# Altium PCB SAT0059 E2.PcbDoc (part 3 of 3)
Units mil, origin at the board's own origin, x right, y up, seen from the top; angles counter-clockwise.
Board outline 3960.27 x 3100.03 mil, 6 copper layers (Top Layer, GND, Power, Inner Routing, GND 2, Bottom Layer), stack 59.2 mil thick; 276 components, 209 nets, 812 pads, 621 vias.
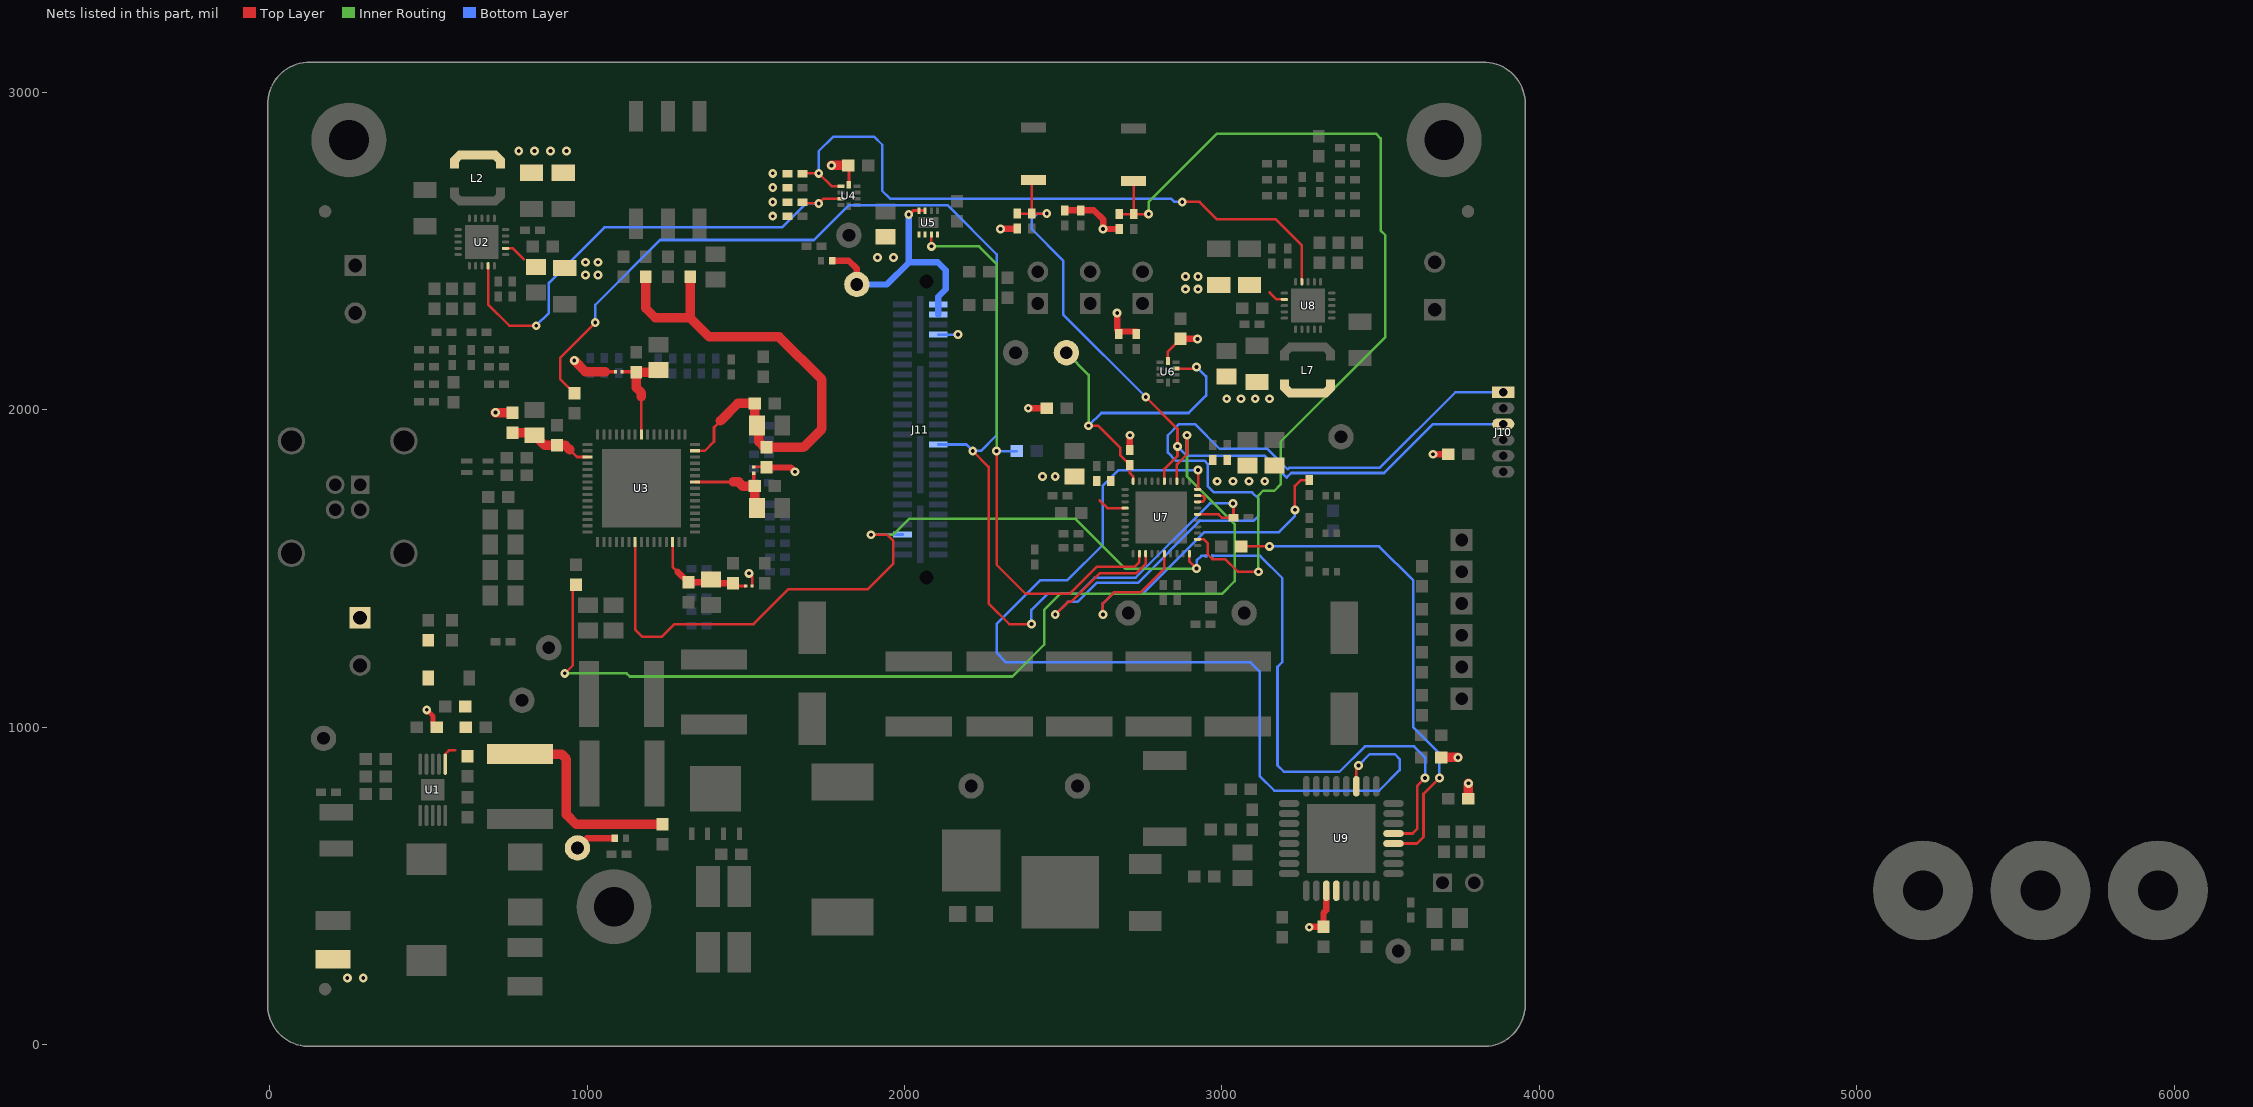
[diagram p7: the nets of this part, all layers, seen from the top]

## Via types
v1: diameter 28, hole 12, Top Layer to Bottom Layer, 528 vias
v2: diameter 19.68, hole 7.87, Top Layer to Bottom Layer, 44 vias
v3: diameter 23.62, hole 11.81, Top Layer to Bottom Layer, 25 vias
v4: diameter 19.68, hole 7.87, Top Layer to Bottom Layer, tented both sides, 20 vias
v5: diameter 18.75, hole 7.87, Top Layer to Bottom Layer, 4 vias

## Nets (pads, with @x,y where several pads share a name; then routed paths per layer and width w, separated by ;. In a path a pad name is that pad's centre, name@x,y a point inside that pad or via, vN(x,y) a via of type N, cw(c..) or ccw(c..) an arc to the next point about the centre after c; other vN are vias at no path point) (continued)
SDA_DRV2667_1: R36.1 U4.1 U8.19 | length 2093.6
  Top Layer w8: R36.1@1676.37,2745 R36.1@1679.35,2745 ; R36.1@1678.34,2743.99 R36.1@1679.35,2745 ; U4.1@1799.8,2704.53 1770.47,2704.53 v1(1730,2745) R36.1@1679.35,2745 ; v1(2875,2655) 2930,2655 2985,2600 3170,2600 3251.68,2518.32 U8.19@3251.68,2403.08
  Bottom Layer w8: v1(1730,2745) 1730,2815 1775,2860 1905,2860 1930,2835 1930,2690 1955,2665 2840,2665 2850,2655 v1(2875,2655)
SDA_DRV2667_2: R38.1 U2.19 U4.3 | length 1535.6
  Top Layer w8: U2.19@688.18,2453.55 688.18,2331.82 755,2265 v1(840,2265) ; R38.1@1676.37,2651.01 1731.01,2651.01 1745.16,2665.16 U4.3@1799.8,2665.16
  Bottom Layer w8: v1(840,2265) 880,2305 880,2400 1055,2575 1614.8,2575 1689.8,2650 v1(1730,2650)
SDA_UC: R50.1 SDA.1 U6.8 U7.10 | length 1088.3
  Top Layer w8: v1(2580,1950) 2610,1950 2680,1880 2680,1856.38 R50.1@2710,1826.38 2710,1800.79 2720.42,1790.37 U7.10@2720.42,1775.17 ; U6.8@2855.2,2129.84 2914.84,2129.84 v1(2920,2135)
  Inner Routing w8: SDA.1@2510,2180 2580,2110 v1(2580,1950)
  Bottom Layer w8: v1(2580,1950) 2620,1990 2895,1990 2950,2045 2950,2105 v1(2920,2135)
SQW: U9.4
SYNC: R59.2 U9.12 | length 1551.3
  Top Layer w8: R59.2@3061.5,1570 v1(3150,1570) ; U9.12@3540.31,633.94 3613.94,633.94 3635,655 3635,790 v1(3685,840)
  Bottom Layer w8: v1(3150,1570) 3495,1570 3602.8,1462.2 3602.8,999.48 3685,917.28 v1(3685,840)
TDIO: C50.1 J10.3 R41.1 RESET.1 U7.5 | length 2423.3
  Top Layer w8: R41.1@2356,2618.26 C50.1@2401,2618.26 ; RESET.1@2406,2723.34 2401,2718.34 C50.1@2401,2618.26 ; v1(2448.26,2618.26) C50.1@2401,2618.26 ; v1(2760,2040) 2860,1940 v1(2860,1885) 2860,1855 2818.84,1813.84 U7.5@2818.84,1775.17
  Bottom Layer w8: v1(2448.26,2618.26) 2418.7,2618.26 2401,2600.56 2401,2569 2500,2470 2500,2300 v1(2760,2040) ; v1(2860,1885) 2890,1855 3135,1855 3203.69,1786.31 3218.37,1801 3511,1801 3665,1955 J10.3@3886,1955
TSC_INT: J11.30 R23.1 R60.2 U7.36 | length 4230.3
  Top Layer w8: R23.1@960,2051.5 915,2096.5 915,2163.94 v1(1026.06,2275) ; v1(2215,1870.52) 2265,1820.52 2265,1390 2330,1325 v1(2400,1325) ; U7.36@2923.17,1670.84 2989.16,1670.84 3000,1660 R60.2@3036.38,1660 3036.38,1703.62 v1(3035,1705)
  Bottom Layer w8: v1(1026.06,2275) 1026.06,2331.06 1230,2535 1715,2535 1825,2645 2135,2645 2290,2490 2290,1920 2240.52,1870.52 v1(2215,1870.52) 2194.76,1890.76 J11.30@2106.1,1890.76 ; v1(2400,1325) 2400,1370 2450,1420 2547.37,1420 2598.37,1471 2728.37,1471 2962.37,1705 v1(3035,1705)
"TX (RX)": J10.1 U7.23 | length 2877.3
  Top Layer w8: v1@2472.5,1357.5 v1(2475,1355) ; v1@2477.5,1357.5 2515,1395 2525,1395 2615,1485 2730,1485 2759.79,1514.79 U7.23@2759.79,1546.83
  Bottom Layer w8: v1(2475,1355) 2515,1395 2545,1395 2605,1455 2735,1455 2930,1650 3100,1650 3115,1665 3115,1720 3095,1740 2975,1740 2955,1760 2955,1830 2946,1839 2856,1839 2830,1865 2830,1920 2865,1955 2915,1955 2993.19,1876.81 3143.19,1876.81 3207.37,1812.63 3211.75,1817 3497,1817 3735,2055 J10.1@3886,2055
UC_INT: R24.1 U7.3 | length 3271.8
  Top Layer w8: v1(930,1170) 955,1195 R24.1@955,1448.5 ; U7.3@2858.21,1775.17 2858.21,1828.21 2890,1860 v1(2890,1920)
  Inner Routing w8: v1(930,1170) 1125,1170 1135,1160 2340,1160 2440,1260 2440,1370 2490,1420 3000,1420 3040,1460 3040,1640 3033.46,1646.54 2890,1790 v1(2890,1920)
USER_BUTTON: C55.1 R49.1 U7.32 USER.1 | length 2871.9
  Top Layer w8: R49.1@2677,2616.62 C55.1@2722,2616.62 ; USER.1@2722,2720.32 C55.1@2722,2616.62 ; v1(2769.26,2616.62) C55.1@2722,2616.62 ; U7.32@2923.17,1592.1 2942.9,1592.1 2955,1580 2955,1545 2970,1530 3010,1530 3050,1490 v1(3115,1490)
  Inner Routing w8: v1(2769.26,2616.62) 2769.26,2654.26 2985,2870 3485,2870 3500,2855 3500,2565 3515,2550 3515,2229.5 3185,1899.5 3185,1765 3165,1745 3130,1745 3115,1730 v1(3115,1490)
USER_LED: R66.2 U7.26 | length 1223
  Top Layer w8: v1(2625,1355) 2625,1390 2660,1425 2744.13,1425 2818.84,1499.71 U7.26@2818.84,1546.83 ; v1(3230,1685) 3230,1760 3248.62,1778.62 R66.2@3275,1778.62
  Bottom Layer w8: v1(2625,1355) 2625,1390 2655,1420 2750,1420 2945,1615 3180,1615 3230,1665 v1(3230,1685)
V_BATTERY: D1.2 J3.1 R8.2
VCC_LCD: D8.2 J11.2 J11.4 TP3.1 U5.7 U5.8 | length 812.6
  Top Layer w10: v1@2015,2615 2027.4,2627.4 U5.8@2045.47,2627.4 U5.7@2065.16,2627.4
  Top Layer w20: D8.2@1772.72,2470 1825,2470 1850,2445 TP3.1@1850,2395
  Bottom Layer w20: TP3.1@1850,2395 1945,2395 2015,2465 ; v1(2013.43,2615) 2013.43,2466.57 2015,2465 ; J11.4@2106.1,2300.2 J11.2@2106.1,2331.7 2106.1,2356.1 2130,2380 2130,2440 2105,2465 2015,2465
VD: J11.47 NT4.2 U3.7 U7.30 | length 2670
  Top Layer w8: U3.7@1151.67,1583.72 1151.67,1308.33 1175,1285 1235,1285 1275,1325 1525,1325 1635,1435 1884.76,1435 1965,1515.24 1965,1586.74 1945.16,1606.58 v1(1895,1606.58) ; U7.30@2897.58,1546.83 2897.58,1522.42 v1(2920,1500)
  Inner Routing w8: v1(1895,1606.58) 1965,1606.58 2014.72,1656.3 2538.7,1656.3 2695,1500 v1(2920,1500)
  Bottom Layer w8: v1@1895,1607.29 J11.47@1993.9,1607.29 ; v1(2920,1500) 2920,1525 2935,1540 NT4.2@2950,1540
VDC_LCD_EN: R111.1 U5.3 U7.22 | length 1833.3
  Top Layer w8: v1@2084.84,2515 U5.3@2084.84,2552.6 ; v1(2290,1870) 2290,1512 2382,1420 2520,1420 2605,1505 2725,1505 2740.1,1520.1 U7.22@2740.1,1546.83
  Inner Routing w8: v1(2085,2515) 2235,2515 2290,2460 v1(2290,1870)
  Bottom Layer w8: v1(2290,1870) R111.1@2353.5,1870
VDD: C23.1 C25.1 C26.1 C28.1 C43.1 C44.1 C52.1 C53.1 C56.1 C58.1 C59.1 C60.1 C61.1 C64.1 C65.1 C66.1 C70.1 C76.2 J11.8 L2.2 L4.2 L5.2 L7.2 NT1.1 NT2.1 NT3.1 R1.2 R5.1 R36.2 R37.2 R38.2 R39.2 R41.2 R47.2 R48.2 R49.2 R50.2 R51.2 R78.1 R80.2 R81.1 R109.2 R110.2 R114.1 TP1.1 U2.2 U4.10 U5.1 U5.2 U5.4 U6.10 U7.14 U7.38 U7.39 U8.2 U9.3 VDD.2 | length 1967.3
  Top Layer w8: U2.2@743.3,2508.67 766.33,2508.67 800,2475 ; v1(1510,1485) 1520,1475 NT2.1@1520,1445 ; NT3.1@1525,1820 1563.5,1820 L5.2@1565,1818.5 ; 2615,1715 2639.47,1690.53 U7.14@2694.83,1690.53 ; U6.10@2830,2153.86 2830,2183.5 C56.1@2870,2223.5 ; U7.38@2921.7,1710.21 2936.85,1710.21 ccw(c2935.33,1720.06) 2936.85,1729.9 U7.39@2921.7,1729.9 ; 3150,2370 3172.04,2347.96 U8.2@3196.56,2347.96
  Top Layer w10: 1056.63,2120 NT1.1@1090,2120 ; C43.1@1823.5,2770 1825,2768.5 1825,2735 U4.10@1825,2708.86
  Top Layer w15: v1(495,1055) 515,1035 515,1011.5 R5.1@526.5,1000
  Top Layer w20: TP1.1@970,620 1000,650 VDD.2@1087.28,650 ; L5.2@1565,1818.5 1641.5,1818.5 v1(1655,1805) ; v1(2302.65,2570.02) R41.2@2354.03,2570.02 ; v1(2390,2005) R114.1@2448.5,2005 ; R109.2@2505,2628.62 R110.2@2555,2628.62 2596.38,2628.62 2625.62,2599.38 v1(2625.62,2569.38) R49.2@2677,2569.38 ; v1(2670,2305) 2670,2251.5 2675,2246.5 R51.2@2730,2246.5 ; R50.2@2710,1873.62 v1(2710,1920) ; C56.1@2870,2223.5 v1(2923.5,2223.5) ; v1(3275,370) 3276.5,371.5 C76.2@3320,371.5 3320,415 3328.7,423.7 U9.3@3328.7,485.31 ; v1(3665,1860) R80.2@3713.5,1860
  Top Layer w30: v1(711.5,1991.5) L4.2@765,1991.5 ; v1(960,2155) 995,2120 1056.63,2120 ; v1(1770,2770) C43.1@1823.5,2770 ; R78.1@3693.5,906.5 3695,905 v1(3743.5,905) ; R81.1@3775,773.5 R81.1@3776.5,775 v1(3776.5,823.5)
  Bottom Layer w8: J11.8@2106.1,2237.21 v1(2168.78,2237.21)
  other v1: 245,210 295,210 2985,1775 3035,1775 3085,1775 3135,1775 2435,1790 2475,1790 3015,2035 3060,2035 3105,2035 3150,2035 2885,2380 2925,2380 2885,2420 2925,2420 995,2425 1035,2425 995,2465 1035,2465 1915,2480 1965,2480 1585,2610 1585,2655 1585,2700 1585,2745 785,2815 835,2815 885,2815 935,2815
VDD33_A: C24.1 C27.1 L4.1 U3.48 | length 269
  Top Layer w8: 945,1875 968.56,1851.44 U3.48@1002.06,1851.44
  Top Layer w30: L4.1@765,1928.5 826.5,1928.5 C24.1@835,1920 866.5,1888.5 C27.1@905,1888.5 931.5,1888.5 945,1875
VDD33_B: C38.1 C40.1 L5.1 R26.2 R28.2 U3.29 | length 1662.2
  Top Layer w8: U3.29@1340.65,1871.12 1371.12,1871.12 1400,1900 1400,1945 1420,1965
  Top Layer w30: R26.2@1185,2418.5 1185,2370 1185,2320 1215,2290 1325,2290 ; R28.2@1325,2418.5 1325,2290 ; 1420,1965 1475,2020 C38.1@1528.5,2020 1528.5,1956.5 C40.1@1535,1950 1541,1944 1541,1900 1559.5,1881.5 L5.1@1565,1881.5 1681.5,1881.5 1740,1940 1740,2095 1605,2230 1385,2230 1325,2290
VDDIO1: C36.1 C37.1 NT2.2 R32.2 U3.13 | length 340.7
  Top Layer w8: U3.13@1269.78,1583.72 1269.78,1505.22 1285,1490
  Top Layer w10: R32.2@1460,1453.5 1468.5,1445 NT2.2@1500,1445
  Top Layer w20: 1285,1490 1318.5,1456.5 C36.1@1320,1456.5 1381.5,1456.5 C37.1@1390,1465 1401.5,1453.5 R32.2@1460,1453.5
VDDIO2: C39.1 C41.1 NT3.2 U3.24 | length 298.1
  Top Layer w8: U3.24@1340.65,1772.7 1460,1772.7
  Top Layer w10: NT3.2@1525,1800 1525,1763.5 C39.1@1528.5,1760
  Top Layer w30: 1460,1772.7 1477.3,1772.7 1490,1760 C39.1@1528.5,1760 C41.1@1528.5,1696.5
VDDIO3: C33.1 C34.1 NT1.2 U3.38 | length 321.3
  Top Layer w8: U3.38@1171.35,1922.3 1171.35,2041.35
  Top Layer w10: NT1.2@1110,2120 1153.5,2120 C33.1@1155,2118.5
  Top Layer w30: 1171.35,2041.35 1171.35,2053.65 1155,2070 C33.1@1155,2118.5 1218.5,2118.5 C34.1@1225,2125
VDDIO/EN: U7.40 U9.19 | length 3018.5
  Top Layer w8: U7.40@2925,1751.41 v1(2925,1810) ; U9.19@3423.19,814.06 3423.19,873.19 v1(3430,880)
  Bottom Layer w8: v1(2925,1810) 2673.8,1810 2625,1761.2 2625,1575 2512.5,1462.5 2427.5,1462.5 2290,1325 2290,1235 2320.39,1204.61 3090.39,1204.61 3119,1176 3119,846 3165,800 3495,800 3560,865 3560,900 3545,915 3465,915 v1(3430,880)
VIN: C8.1 C18.1 R11.1 R15.1 R112.2 U1.1 | length 710.7
  Top Layer w8: U1.1@553.37,883.71 553.37,915.39 565,927.02 584.87,927.02
  Top Layer w30: C18.1@789,915.36 919.64,915.36 935,900 935,725 966,694 R112.2@1237.5,694
VSYNC: NT4.1 U9.13 | length 1682.2
  Top Layer w8: U9.13@3540.31,665.43 3600.43,665.43 3615,680 3615,815 v1(3640,840)
  Bottom Layer w8: NT4.1@2970,1540 3120,1540 3190,1470 3190,1205 3175,1190 3175,880 3195,860 3370,860 3450,940 3605,940 3640,905 v1(3640,840)
pads on no net: FID1.1 FID2.1 FID3.1 FID4.1 FID5.1 FID6.1 H1.1 H2.1 H3.1 J11.57 J11.58 U2.9 U3.54 U8.9 U9.14

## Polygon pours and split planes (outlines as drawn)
GND on Top Layer "Top Layer - GND Rosenberger" (solid, pour order 6): 90,1470 110,1470 155,1425 380,1425 425,1470 584,1470 584,1960 425,1960 380,2005 155,2005 110,1960 90,1960
V_BATTERY on Top Layer "Top Layer- V_BATTERY" (solid, remove dead copper, pour order 5): 525,1105 525,1295 460.67,1295 350.67,1405 220,1405 220,1285 275,1285 455,1105
GND on Bottom Layer "Top Layer - GND Rosenberger" (solid, pour order 4): 90,1490 584,1490 584,1960 90,1960
GND on GND (split plane): 3934.11,113.26 3934.04,112.6 3934.11,113.26 3934.54,114.68
GND on GND (split plane): 3820,3073.67 3820,3074.78 3821.74,3074.61 3822.26,3074.66 3822.27,3074.62 3825.13,3074.73 3833.76,3074.39 3842.34,3073.38 3850.81,3071.69 3859.12,3069.35 3867.23,3066.36 3875.07,3062.74 3882.61,3058.52 3889.79,3053.72 3896.57,3048.38 3902.91,3042.51 3908.78,3036.17 3914.12,3029.39 3918.92,3022.21 3923.14,3014.67 3926.76,3006.83 3929.75,2998.72 3932.09,2990.41 3933.78,2981.94 3934.79,2973.36 3935.11,2965.32 3935.05,2964.73 3935.11,2964.14 3934.94,2959.79 3935.01,2959.79 3934.92,2958.89 3934.92,115.94 3934.54,114.68 3933.67,112.6 3934.04,112.6 3933.96,111.73 3933.86,111.74 3933.38,107.66 3931.69,99.19 3929.35,90.88 3926.36,82.77 3922.74,74.93 3918.52,67.39 3913.72,60.21 3908.38,53.43 3902.51,47.09 3896.17,41.22 3889.39,35.88 3882.21,31.08 3874.67,26.86 3866.83,23.24 3858.72,20.25 3850.41,17.91 3841.94,16.22 3833.36,15.21 3824.73,14.87 3819.79,15.06 3819.79,14.99 3818.89,15.08 130.11,15.08 129.21,14.99 129.21,15.06 124.27,14.87 115.64,15.21 107.06,16.22 98.59,17.91 90.28,20.25 82.17,23.24 74.33,26.86 66.79,31.08 59.61,35.88 52.83,41.22 46.49,47.09 40.62,53.43 35.28,60.21 30.48,67.39 26.26,74.93 22.64,82.77 19.65,90.88 17.31,99.19 15.62,107.66 15.32,110.26 16.22,112.43 15.57,114 15.08,113.95 15.08,2958.89 14.99,2959.79 15.06,2959.79 14.87,2964.73 15.21,2973.36 16.22,2981.94 17.91,2990.41 20.25,2998.72 23.24,3006.83 26.86,3014.67 31.08,3022.21 35.88,3029.39 41.22,3036.17 47.09,3042.51 53.43,3048.38 60.21,3053.72 67.39,3058.52 74.93,3062.74 82.77,3066.36 90.88,3069.35 99.19,3071.69 107.66,3073.38 116.24,3074.39 124.87,3074.73 127.73,3074.62 127.74,3074.66 128.26,3074.61 130,3074.78 130,3073.67 133.01,3074.92 3816.99,3074.92
VDD on Power (split plane): 3934.11,113.26 3934.04,112.6 3934.11,113.26 3934.54,114.68
VDD on Power (split plane): 3820,3073.67 3820,3074.78 3821.74,3074.61 3822.26,3074.66 3822.27,3074.62 3825.13,3074.73 3833.76,3074.39 3842.34,3073.38 3850.81,3071.69 3859.12,3069.35 3867.23,3066.36 3875.07,3062.74 3882.61,3058.52 3889.79,3053.72 3896.57,3048.38 3902.91,3042.51 3908.78,3036.17 3914.12,3029.39 3918.92,3022.21 3923.14,3014.67 3926.76,3006.83 3929.75,2998.72 3932.09,2990.41 3933.78,2981.94 3934.79,2973.36 3935.11,2965.32 3935.05,2964.73 3935.11,2964.14 3934.94,2959.79 3935.01,2959.79 3934.92,2958.89 3934.92,115.94 3934.54,114.68 3933.67,112.6 3934.04,112.6 3933.96,111.73 3933.86,111.74 3933.38,107.66 3931.69,99.19 3929.35,90.88 3926.36,82.77 3922.74,74.93 3918.52,67.39 3913.72,60.21 3908.38,53.43 3902.51,47.09 3896.17,41.22 3889.39,35.88 3882.21,31.08 3874.67,26.86 3866.83,23.24 3858.72,20.25 3850.41,17.91 3841.94,16.22 3833.36,15.21 3824.73,14.87 3819.79,15.06 3819.79,14.99 3818.89,15.08 130.11,15.08 129.21,14.99 129.21,15.06 124.27,14.87 115.64,15.21 107.06,16.22 98.59,17.91 90.28,20.25 82.17,23.24 74.33,26.86 66.79,31.08 59.61,35.88 52.83,41.22 46.49,47.09 40.62,53.43 35.28,60.21 30.48,67.39 26.26,74.93 22.64,82.77 19.65,90.88 17.31,99.19 15.62,107.66 15.32,110.26 16.22,112.43 15.57,114 15.08,113.95 15.08,2958.89 14.99,2959.79 15.06,2959.79 14.87,2964.73 15.21,2973.36 16.22,2981.94 17.91,2990.41 20.25,2998.72 23.24,3006.83 26.86,3014.67 31.08,3022.21 35.88,3029.39 41.22,3036.17 47.09,3042.51 53.43,3048.38 60.21,3053.72 67.39,3058.52 74.93,3062.74 82.77,3066.36 90.88,3069.35 99.19,3071.69 107.66,3073.38 116.24,3074.39 124.87,3074.73 127.73,3074.62 127.74,3074.66 128.26,3074.61 130,3074.78 130,3073.67 133.01,3074.92 3816.99,3074.92
GND on GND 2 (split plane): 3934.11,113.26 3934.04,112.6 3934.11,113.26 3934.54,114.68
GND on GND 2 (split plane): 3820,3073.67 3820,3074.78 3821.74,3074.61 3822.26,3074.66 3822.27,3074.62 3825.13,3074.73 3833.76,3074.39 3842.34,3073.38 3850.81,3071.69 3859.12,3069.35 3867.23,3066.36 3875.07,3062.74 3882.61,3058.52 3889.79,3053.72 3896.57,3048.38 3902.91,3042.51 3908.78,3036.17 3914.12,3029.39 3918.92,3022.21 3923.14,3014.67 3926.76,3006.83 3929.75,2998.72 3932.09,2990.41 3933.78,2981.94 3934.79,2973.36 3935.11,2965.32 3935.05,2964.73 3935.11,2964.14 3934.94,2959.79 3935.01,2959.79 3934.92,2958.89 3934.92,115.94 3934.54,114.68 3933.67,112.6 3934.04,112.6 3933.96,111.73 3933.86,111.74 3933.38,107.66 3931.69,99.19 3929.35,90.88 3926.36,82.77 3922.74,74.93 3918.52,67.39 3913.72,60.21 3908.38,53.43 3902.51,47.09 3896.17,41.22 3889.39,35.88 3882.21,31.08 3874.67,26.86 3866.83,23.24 3858.72,20.25 3850.41,17.91 3841.94,16.22 3833.36,15.21 3824.73,14.87 3819.79,15.06 3819.79,14.99 3818.89,15.08 130.11,15.08 129.21,14.99 129.21,15.06 124.27,14.87 115.64,15.21 107.06,16.22 98.59,17.91 90.28,20.25 82.17,23.24 74.33,26.86 66.79,31.08 59.61,35.88 52.83,41.22 46.49,47.09 40.62,53.43 35.28,60.21 30.48,67.39 26.26,74.93 22.64,82.77 19.65,90.88 17.31,99.19 15.62,107.66 15.32,110.26 16.22,112.43 15.57,114 15.08,113.95 15.08,2958.89 14.99,2959.79 15.06,2959.79 14.87,2964.73 15.21,2973.36 16.22,2981.94 17.91,2990.41 20.25,2998.72 23.24,3006.83 26.86,3014.67 31.08,3022.21 35.88,3029.39 41.22,3036.17 47.09,3042.51 53.43,3048.38 60.21,3053.72 67.39,3058.52 74.93,3062.74 82.77,3066.36 90.88,3069.35 99.19,3071.69 107.66,3073.38 116.24,3074.39 124.87,3074.73 127.73,3074.62 127.74,3074.66 128.26,3074.61 130,3074.78 130,3073.67 133.01,3074.92 3816.99,3074.92

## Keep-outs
Keep-Out Layer:
  text ".Layer_Name" at 577,-858.49 h60

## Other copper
Top Layer:
  region net VDD: 1900,2575 1900,2470 1925,2445 2105,2445 2140,2480 2140,2544 2121,2563 2099,2563 2099,2542 2112,2529 2112,2501 2100,2489 2071,2489 2059,2501 2059,2531 2070,2542 2070,2563 1992,2563 1980,2575
  region net GND: 2950,2480 3125,2480 3135,2490 3220,2490 3220,2525 3160,2585 2950,2585
  region net VDD: 2980,2130 3050,2130 3060,2120 3360,2120 3360,2020 3005,2020 2980,2045
  region net NetC80_1: 3348,2250 3348,2257 3365,2274 3365,2279 3359,2285 3359,2292 3365,2292 3364,2305 3359,2305 3359,2312 3463,2312 3475,2300 3475,2250
  region net NetL7_1: 3180,2155 3360,2155 3360,2190 3330,2220 3286,2220 3275,2231 3275,2242 3268,2242 3268,2233 3255,2233 3255,2242 3248,2242 3248,2231 3237,2220 3210,2220 3180,2190
  region net GND: 680,675 680,790 895,790 895,675
  region net VIN: 895,880 610,880 595,895 595,905 575,925 575,930 595,950 595,1085 645,1085 645,975 670,950 895,950
  region net NetC7_1: 430,635 507,635 530,658 553,658 605,710 605,740 645,740 645,665 675,635 860,635 860,530 430,530
  region net NetC1_1: 560,215 400,215 260,355 145,355 145,645 270,645 270,610 560,320
  region net GND: 970,1235 1115,1235 1115,1330 970,1330
  region net GND: 800,1970 875,1970 885,1960 885,1930 925,1930 925,2030 885,2070 815,2070 815,2040 800,2025
  region net GND: 2655,840 2985,840 2985,925 2655,925
  region net NetQ1_1: 1420,430 1420,555 1445,580 1445,690 1315,690 1315,455 1340,430
  region net NetQ2_3: 2705,535 2705,650.16 2755.04,700.2 2755.24,700 2985,700 2985,640 2965,620 2895,620 2810,535
  region net GND: 975,1220 1080,1220 1080,740 975,740
  region net NetD3_1: 1705,460 2320,460 2365,505 2365,755 2485,875 2615,875 2615,230 1705,230
  region net GND: 1295,1290 1545,1290 1655,1400 1770,1400 1880,1290 3220,1290 3330,1400 3490,1400 3490,1175 1295,1175
  region net FB: 2310,480 2110,480 2110,845 2190,925 2190,1045 2260,1115 3435,1110 3435,1050 3450,1035 3450,1015 3435,1000 3435,940 3120,940 3105,925 3085,925 3070,940 2505,940 2310,745
  region net NetC30_1: 1175,730 1175,1215 1270,1215 1280,1205 1280,1170 1335,1115 2085,1115 2155,1045 2155,930 1955,730
  region net GND: 120,2990 120,3090 3840,3090 3840,2990
  region net GND: 3950,115 3850,115 3850,1770 3930,1770 3930,2100 3850,2100 3850,2975 3950,2975
  region net GND: 100,115 0,115 0,2970 100,2970
  region net GND: 115,0 115,100 3835,100 3835,0
  region net GND: 156.85,675 315,675 315,760 156.85,760
  region net NetD2_2: 745,275 865,275 865,465 745,465
  region net GND: 2275,3075 2275,2725 1975,2725 1975,3075
  region net GND: 925,25 925,555 1230,555 1230,400 1300,330 1300,25
  region net GND: 3450,25 3450,200 3875,200 3875,25
  region net GND: 3865,2685 3535,2685 3535,3015 3865,3015
  region net GND: 85,2685 415,2685 415,3015 85,3015
  region net NetC3_1: 591.86,2607 591.86,2599.63 574.86,2582.63 574.86,2577.63 580.86,2571.63 580.86,2564.63 574.86,2564.63 575.86,2551.63 580.86,2551.63 580.86,2544.63 450.37,2544.63 450,2545 450,2607
  region net VDD: 965,2720 965,2815 935,2845 590,2845 565,2820 565,2755 740,2755 775,2720
  region net VDD: 2870,2365 2870,2435 3115,2435 3155,2395 3155,2365
  region net VDD: 795,2410 795,2480 1050,2480 1050,2410
  region net GND: 705,2375 785,2375 805,2395 970,2395 970,2300 740,2300 705,2335
  region net VDD: 2665,1795 2590,1795 2570,1815 2420,1815 2420,1760 2565,1760 2615,1710 2625,1710 2625,1735 2645,1755 2665,1755
  region net VDD: 2927,1706 2963,1706 3014,1757 3167,1757 3200,1790 3200,1860 2955,1860 2955,1745 2944,1734 2927,1734 2927,1727 2942,1727 2942,1713 2927,1713
  region net GND: 2955,1872 2955,1965 3167,1965 3200,1932 3200,1872
  region net VDD: 1650,2595 1565,2595 1565,2760 1650,2760
  region net GND: 1570,1780 1650,1780 1690,1740 1690,1700 1645,1655 1585,1655 1585,1725 1570,1740
  region net VDD: 145,235 145,300 285,300 325,260 325,190 245,190 200,235
  region net NetL2_1: 743,2668 743,2701 567,2701 566,2702 566,2660 602,2624 657,2624 664,2617 664,2607 673,2607 673,2624 684,2624 684,2607 692,2607 692,2617
  region net GND: 1135,2160 1175,2160 1190,2175 1260,2175 1260,2245 1150,2245 1135,2230
  text ".Layer_Name" at 577,-858.49 h60
Inner Routing:
  text ".Layer_Name" at 577,-858.49 h60
Bottom Layer:
  region net GND: 115,0 115,100 3835,100 3835,0
  region net GND: 100,115 0,115 0,2970 100,2970
  region net GND: 120,2990 120,3090 3840,3090 3840,2990
  region net GND: 2275,3075 2275,2725 1975,2725 1975,3075
  region net GND: 925,25 925,300 1300,300 1300,25
  region net GND: 3450,25 3450,200 3875,200 3875,25
  region net GND: 3950,115 3850,115 3850,1770 3930,1770 3930,2100 3850,2100 3850,2975 3950,2975
  region net GND: 3865,2685 3535,2685 3535,3015 3865,3015
  region net GND: 85,2685 415,2685 415,3015 85,3015
  text ".Layer_Name" at 577,-858.49 h60
GND (plane layer: these items are gaps in the copper):
  region: 206.69,1685.63 284.8,1685.63 285.43,1685 285.43,1764.37 206.69,1764.37
  region: 2885,2380 2925,2380 2925,2420 2885,2420
  region: 995,2425 1035,2425 1035,2465 995,2465
  text ".Layer_Name" at 577,-858.49 h60
Power (plane layer: these items are gaps in the copper):
  region: 2777.5,1661 2809,1692.5 2840.5,1661 2809,1629.5
  region: 2920,855 2970,855 2970,905 2920,905
  region: 2670,855 2720,855 2720,905 2670,905
  region: 950,275 1000,275 1000,325 950,325
  region: 1200,275 1250,275 1250,325 1200,325
  region: 100,2700 400,2700 400,3000 100,3000
  region: 3550,2700 3850,2700 3850,3000 3550,3000
  region: 206.69,1685.63 284.8,1685.63 285.43,1685 285.43,1764.37 206.69,1764.37
  region: 3235.93,2363.71 3306.79,2363.71 3306.79,2292.84 3235.93,2292.84
  region: 633.07,2563.79 703.93,2563.79 703.93,2492.92 633.07,2492.92
  region: 1092.61,1831.75 1250.1,1831.75 1250.1,1674.27 1092.61,1674.27
  region: 494.32,783.31 533.68,783.31 533.68,783.32 533.68,822.68 494.31,822.68
  region: 3277.52,551.26 3474.37,551.26 3474.37,748.11 3277.52,748.11
  text ".Layer_Name" at 577,-858.49 h60
GND 2 (plane layer: these items are gaps in the copper):
  region: 206.69,1685.63 284.8,1685.63 285.43,1685 285.43,1764.37 206.69,1764.37
  region: 2885,2420 2885,2380 2925,2380 2925,2420
  region: 995,2465 1035,2465 1035,2425 995,2425
  text ".Layer_Name" at 577,-858.49 h60

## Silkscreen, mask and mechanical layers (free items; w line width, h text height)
Top Overlay:
  lines w7: 615,2025 615,2050 695,2050 695,2025 ; 640,2050 640,2100 ; 1427.5,2367.5 1435,2360 1495,2360 ; 1529.28,2415 1495,2415 1495,2320 1530,2320 ; 3105,2860 3105,2835 3190,2835 3190,2860 ; 3150,2835 3150,2815 3250,2815 3250,2780 ; 3465,2570 3505,2610 3525,2610 ; 3550,2570 3525,2570 3525,2652 3550,2652
  text "only one on at a time" at 1025,2925 h40 r270
  text "7b I2C Address" at 1480,2910 h60 r270
  text "GND" at 1680,2550 h40
  text "OUT-" at 3700,2550 h50
  text "OUT+" at 130,2545 h50
  text "ON" at 1535,2515 h60 r270
  text "VDD_LCD" at 1610,2420 h40
  text "2C" at 1345,2360 h60 r270
  text "38" at 1140,2355 h60 r270
  text "32" at 1240,2355 h60 r270
  text "VDD_LCD" at 1740,2300 h40
  text "OUT+" at 3700,2190 h50
  text "OUT-" at 130,2180 h50
  text "GND" at 3345,1985 h40
  text "USER" at 3435,1715 h40
  text "LOCK" at 3440,1600 h40
  text "PASS" at 3435,1480 h40
  text "VBAT" at 140,1435 h50
  text "GND" at 140,1075 h50
  text "GND" at 900,1050 h40 r90
  text "LOOP" at 125,1035 h45
  text "VDD" at 925,690 h40
  text "SAT0059 Rev. E2" at 2710,167 h90
  text ".Layer_Name" at 577,-858.49 h60
Bottom Overlay:
  text ".Layer_Name" at 577,-858.49 h60
Top Paste:
  text ".Layer_Name" at 577,-858.49 h60
Bottom Paste:
  text ".Layer_Name" at 577,-858.49 h60
Top Solder:
  region: 115,0 115,100 3835,100 3835,0
  region: 100,115 0,115 0,2970 100,2970
  region: 120,2990 120,3090 3840,3090 3840,2990
  region: 3450,25 3450,200 3875,200 3875,25
  region: 925,25 925,300 1300,300 1300,25
  region: 2275,3075 2275,2725 1975,2725 1975,3075
  region: 3950,115 3850,115 3850,1770 3915,1770 3915,2100 3850,2100 3850,2975 3950,2975
  region: 3865,2685 3535,2685 3535,3015 3865,3015
  region: 85,2685 415,2685 415,3015 85,3015
  lines w100: 50,118 ccw(c118,118.01) 120.22,50.05 ; 50,2972 cw(c118,2971.99) 120.22,3039.95 ; 3829.78,3039.95 cw(c3832,2971.99) 3900,2972 ; 3830,50 ccw(c3832.22,117.96) 3900.22,117.95
  text ".Layer_Name" at 577,-858.49 h60
  text ".Layer_Name" at 577,-858.49 h60
Bottom Solder:
  region: 115,0 115,100 3835,100 3835,0
  region: 100,115 0,115 0,2970 100,2970
  region: 120,2990 120,3090 3840,3090 3840,2990
  region: 3450,25 3450,200 3875,200 3875,25
  region: 925,25 925,300 1300,300 1300,25
  region: 2275,3075 2275,2725 1975,2725 1975,3075
  region: 3950,115 3850,115 3850,1770 3915,1770 3915,2100 3850,2100 3850,2975 3950,2975
  region: 3865,2685 3535,2685 3535,3015 3865,3015
  region: 85,2685 415,2685 415,3015 85,3015
  lines w100: 50,118 ccw(c118,118.01) 120.22,50.05 ; 50,2972 cw(c118,2971.99) 120.22,3039.95 ; 3829.78,3039.95 cw(c3832,2971.99) 3900,2972 ; 3830,50 ccw(c3832.22,117.96) 3900.22,117.95
  text ".Layer_Name" at 577,-858.49 h60
Drill Guide:
  text ".Layer_Name" at 577,-858.49 h60
M1 Board Outline:
  lines w10: -0.11,112.43 ccw(c124.27,124.87) 130,0 3820,0 ; 0,112.6 0,2960 ; 0,2959 cw(c124.87,2964.73) 129.98,3089.63 ; 130,3090 3820,3090 ; 3819,0 ccw(c3824.73,124.87) 3949.11,112.43 ; 3820.02,3089.63 cw(c3825.13,2964.73) 3950,2959 ; 3950,112.6 3950,2960
  text ".Layer_Name" at 577,-858.49 h60
M2 Board Dimensions:
  rectangle: -0.5,-285.5 124.5,-160.5
  rectangle: 124.5,-410.5 499.5,-285.5
  lines w7: -0.5,-285.5 999.5,-285.5 ; 124.5,-410.5 124.5,-160.5 ; 249.5,-410.5 249.5,-160.5 ; 499.5,-410.5 499.5,-160.5 ; 749.5,-410.5 749.5,-160.5 ; -0.5,-410.5 999.5,-410.5 999.5,-160.5 -0.5,-160.5 -0.5,-410.5
  lines w10: -0.5,-475.5 -0.5,-455.5 ; 59.5,-485.5 -0.5,-465.5 ; 59.5,-445.5 -0.5,-465.5 ; 223.58,-465.5 -0.5,-465.5 ; 775.42,-465.5 999.5,-465.5 ; 939.5,-485.5 999.5,-465.5 ; 939.5,-445.5 999.5,-465.5 ; 999.5,-475.5 999.5,-455.5
  text "1000 (mil)" at 233.58,-501.49 h60
  text ".Layer_Name" at 577,-858.49 h60
M3 3D STEP Top:
  text ".Layer_Name" at 577,-858.49 h60
M4 3D STEP Bottom:
  text ".Layer_Name" at 577,-858.49 h60
M5 Assembly Top:
  lines w7: 5588.36,-4.5 6713.36,-4.5 ; 5588.36,118 6710.86,118 ; 5903.36,-124.5 5903.36,238 ; 6288.36,-124.5 5588.36,-124.5 ; 6288.36,238 5588.36,238 ; 5588.36,-124.5 6713.36,-124.5 6713.36,238 5588.36,238 ; 5588.36,-124.5 5588.36,238
  lines w10: -292,-930.17 6308,-930.17 ; -292,-726.83 6310,-726.83 ; -292,-523.5 -292,-1133.5 3713,-1133.5 6310,-1133.5 6310,-523.5 -291.5,-523.5 -291.5,-1133.5 1284,-1133.5 ; 2173,-1133.5 2173,-523.5 ; 3440,-726.83 3440,-523.5 ; 4280,-726.83 4280,-523.5 ; 4902,-1140 4902,-937.17
  text "TABLE 1" at 5975.86,273 h40
  text "Variant" at 5613.36,163 h40
  text "Label text" at 6048.36,163 h40
  text "001" at 5680.86,43 h40
  text "ChangeMe!" at 5958.36,40.5 h40
  text "002" at 5680.86,-82 h40
  text "ChangeMe!" at 5953.36,-84.5 h40
  text "COMPONENTS MARKED 'DNP' SHOULD NOT BE POPULATED." at 1153.5,-318.5 h60
  text "ASSEMBLY VARIANT:" at 1153,-434 h60
  text ".VariantName" at 2189,-434 h60
  text "PCB VIEWED FROM TOP SIDE" at -228.5,-655.67 h60
  text "BOARD #:" at 2248,-655.67 h60
  text ".PRJ_Number" at 2793.5,-655.67 h60
  text "REV:" at 3638,-655.67 h60
  text ".PCB_Rev" at 3929.5,-655.67 h60
  text ".VersionControl_RevNumber" at 4982,-655.67 h60
  text "IGNORE ->" at -228.5,-858.49 h60
  text "PLOT NAME =" at -228.5,-1064.34 h60
  text ".plot_File_Name" at 577,-1064.34 h60
  text "GENERATED    :" at 2250,-1064.34 h60
  text ".Print_Date" at 3119.5,-1064.34 h60
  text ".Print_Time" at 3848.5,-1064.34 h60
  text "TEXAS INSTRUMENTS" at 5113,-1064.34 h60
  text "SVN REV:" at 3826,-1130.67 h60
M6 Assembly Bottom:
  lines w10: -292.5,-727.33 6309.5,-727.33 ; -290.5,-930.67 6309.5,-930.67 ; 1115.5,-1140.5 1115.5,-937.67 ; 1737.5,-727.33 1737.5,-524 ; 2577.5,-727.33 2577.5,-524 ; 3844.5,-1134 3844.5,-524 ; 4733.5,-1134 6309,-1134 6309,-524 -292.5,-524 -292.5,-1134 2304.5,-1134 6309.5,-1134 6309.5,-524
  text "COMPONENTS MARKED 'DNP' SHOULD NOT BE POPULATED." at 6102,-318 h60
  text ".VariantName" at 5058,-434 h60
  text "ASSEMBLY VARIANT:" at 6097,-434 h60
  text ".VersionControl_RevNumber" at 1035.5,-656.17 h60
  text "SVN REV:" at 1541.5,-656.17 h60
  text ".PCB_Rev" at 2088,-656.17 h60
  text "REV:" at 2379.5,-656.17 h60
  text ".PRJ_Number" at 3224,-656.17 h60
  text "BOARD #:" at 3769.5,-656.17 h60
  text "PCB VIEWED FROM BOTTOM SIDE" at 6246,-656.17 h60
  text "IGNORE ->" at 2547.85,-858.49 h60
  text "TEXAS INSTRUMENTS" at 904.5,-1064.84 h60
  text ".Print_Time" at 2169,-1064.84 h60
  text ".Print_Date" at 2898,-1064.84 h60
  text "GENERATED    :" at 3767.5,-1064.84 h60
  text ".plot_File_Name" at 5440.5,-1064.84 h60
  text "PLOT NAME =" at 6246,-1064.84 h60
M9 Title Sheet:
  drawing of 57 lines, arcs and shapes, not listed
  text "1" at 739.84,8036.5 h70
  text "2" at 3235.5,8036.5 h70
  text "3" at 5724.84,8036.5 h70
  text "4" at 8231.51,8036.5 h70
  text "5" at 10730.5,8036.5 h70
  text "6" at 13235.5,8036.5 h70
  text "A" at -416.5,6893.5 h70
  text "A" at 14383.5,6893.5 h70
  text "B" at -416.5,4513.5 h70
  text "B" at 14383.5,4513.5 h70
  text "C" at -416.5,2138.5 h70
  text "C" at 14383.5,2138.5 h70
  text "PROJECT TITLE:" at 11343.5,277.5 h45
  text ".PRJ_Title" at 11393.5,144.17 h70
  text "DESIGNED FOR:" at 11343.5,-23.5 h45
  text ".PRJ_Customer" at 11393.5,-163.5 h70
  text "D" at -416.5,-231.5 h70
  text "D" at 14383.5,-231.5 h70
  text "FILE NAME:" at 11343.5,-323.5 h45
  text ".PCB_File_Name_No_Path" at 11393.5,-443.5 h70
  text "Texas Instruments (TI) and/or its licensors do not warrant the accuracy or completeness of this specification" at 6374,-605.34 h45
  text "ENGINEER:" at 11343.5,-613.5 h45
  text "LAYOUT BY:" at 12848.5,-613.5 h45
  text "or any information contained therein. TI and/or its licensors do not warrant that this design will meet" at 6329.01,-718 h45
  text ".PRJ_Engineer" at 11393.5,-768.49 h70
  text ".PCB_Layout" at 12899,-768.49 h70
  text "the specifications, will be suitable for your application or fit for any particular purpose, or will operate in" at 6329.01,-830.67 h45
  text ".Layer_Name" at 577,-858.49 h60
  text "ALTIUM DESIGNER VERSION:" at 12848.5,-923.5 h45
  text "an implementation. TI and/or its licensors do not warrant that the design is production worthy. You should" at 6329.01,-943.33 h45
  text "completely validate and test your design implementation to confirm the system functionality for your application." at 6374,-1056 h45
  text ".print_Scale" at 11393.5,-1056.83 h70
  text ".Application_BuildNumber" at 12899,-1056.83 h70
  text "1" at 739.84,-1263.5 h70
  text "2" at 3235.5,-1263.5 h70
  text "3" at 5724.84,-1263.5 h70
  text "4" at 8231.51,-1263.5 h70
  text "5" at 10730.5,-1263.5 h70
  text "6" at 13235.5,-1263.5 h70
M10 Fab Notes:
  drawing of 212 lines, arcs and shapes, not listed
  text "DESIGN INFORMATION" at 12381.02,6810 h60
  text "(REFER ALSO ARRAY/PANEL PROFILING INFORMATION)" at 12019.46,6648.29 h60
  text "BOARD SIZE" at 11333.46,6644 h60
  text "3950MIL" at 11795.78,6516.18 h60
  text "X" at 12301.46,6516.18 h60
  text "3090MIL" at 12532.78,6516.18 h60
  text "Number of Layers :" at 11736.46,6319 h60
  text "6" at 12831.27,6309 h60
  text "MIN. TRACK WIDTH:" at 11736.46,6180 h60
  text "8" at 12832.7,6180 h60
  text "MIL" at 12987.46,6180 h60
  text "MIN. CLEARANCE:" at 11736.46,6048 h60
  text "5" at 12832.7,6048 h60
  text "MIL" at 12987.46,6048 h60
  text "MIN. VIA PAD SIZE:" at 11736.46,5916 h60
  text "24" at 12802.71,5916 h60
  text "MIL" at 12987.46,5916 h60
  text "0.05mm (2MIL)" at 12431.46,5774.29 h60
  text "MINIMUM ANNULAR RING" at 11407.23,5770 h60
  text "EXTERNAL" at 13139.46,5770 h60
  text "PER" at 11607.23,5652 h60
  text "IPC-D-275 CLASS 2 LEVEL C" at 11827.23,5652 h60
  text "MIL, HOLES" at 13315.46,5539.71 h60
  text "+/-" at 12923,5539 h60
  text "+/-" at 13777,5539 h60
  text "REGISTRATION TOLERANCES:" at 11407.23,5534 h60
  text "METAL" at 12607,5534 h60
  text "5" at 13183.2,5534 h60
  text "3" at 14016.2,5534 h60
  text "MIL" at 14132.46,5534 h60
  text "MATERIAL:" at 11332.46,5324.54 h60
  text "FR-4 High Tg" at 12318.9,5184.21 h60
  text "FR-408" at 11753.46,5175.64 h60
  text "X" at 12165.46,5175.64 h60
  text "OTHER" at 13241.46,5175.64 h60
  text "62 MIL (1.6mm) +/-10%" at 12073.56,5012.92 h60
  text "THICKNESS:" at 11407.23,5008.64 h60
  text "X" at 11945.4,5008.64 h60
  text "OTHER" at 13358.46,5008.64 h60
  text "TOLERANCE:" at 11407.23,4850.64 h60
  text "X" at 12246.53,4850.64 h60
  text "ANSI IPC-6012 TYPE 3 CLASS 2" at 12433.48,4850.64 h60
  text "OTHER +/-" at 12433.46,4694.64 h60
  text "BOW & TWIST:" at 11407.23,4537.64 h60
  text "X" at 12246.53,4537.64 h60
  text "ANSI IPC-6012 TYPE 3 CLASS 2" at 12433.48,4537.64 h60
  text "OTHER +/-" at 12433.46,4379.13 h60
  text "COPPER THICKNESS (FINISHED):" at 11332.46,4243.64 h60
  text "1.4MIL (1oz)" at 12212.46,4090.92 h60
  text "2MIL (1.4oz)" at 12979.46,4090.92 h60
  text "2.8MIL (2oz)" at 13706.46,4090.92 h60
  text "OUTER:" at 11689.46,4086.64 h60
  text "X" at 12084,4086 h60
  text "1.4MIL (1oz)" at 12212.46,3933.92 h60
  text "2.8MIL (2oz)" at 12979.46,3933.92 h60
  text "N/A" at 13706,3934.29 h60
  text "INNER SIGNAL:" at 11400.38,3929.64 h60
  text "X" at 12085.42,3929.64 h60
  text "DRILLING:" at 11332.46,3790.64 h60
  text "REFERENCE:" at 11407.23,3673.64 h60
  text "X" at 12055.46,3673.64 h60
  text "AS SHOWN" at 12242.46,3673.64 h60
  text "X" at 12956.46,3673.64 h60
  text "NC_DRILL FILES" at 13093.46,3673.64 h60
  text "PTH MIN COPPER THICKNESS:" at 11407.23,3515.64 h60
  text "X" at 12757.46,3515.64 h60
  text "1MIL" at 12894.46,3515.64 h60
  text "OTHER" at 13391.46,3515.64 h60
  text "BOARD FINISH:" at 11332.46,3356.64 h60
  text "SILKSCREEN:" at 11487.68,3238.64 h60
  text "X" at 12436.46,3238.64 h60
  text "TOP" at 12562.46,3238.64 h60
  text "X" at 12946.46,3238.64 h60
  text "BOTTOM" at 13073.46,3238.64 h60
  text "SILKSCREEN COLOR:" at 11487.68,3071.64 h60
  text "X" at 12435.42,3071.64 h60
  text "WHITE" at 12562.46,3071.64 h60
  text "OTHER" at 13073.46,3071.64 h60
  text "SOLDER RESIST COLOR:" at 11487.68,2901.64 h60
  text "BLACK" at 13796.46,2747.44 h60
  text "X" at 13160,2745 h60
  text "GREEN" at 12182.46,2742.44 h60
  text "BLUE" at 12773.46,2742.44 h60
  text "OTHER" at 13311.46,2742.44 h60
  text "IMMERSION GOLD (ENIG)" at 12393.46,2553.92 h60
  text "ENEPIG" at 13731,2550.64 h60
  text "SURFACE FINISH:" at 11332.46,2549.64 h60
  text "X" at 12206.51,2549.64 h60
  text "IMM. TIN/SILVER OR EQUIV" at 11662,2392.64 h60
  text "OTHER" at 13093.46,2392.64 h60
  text "ARRAY/PANEL:" at 11332.46,2213.64 h60
  text "CUT AND TRIM PER MECH LAYER 1" at 12393.46,2209.35 h60
  text "N.C. ROUTE" at 12393.46,2057.64 h60
  text "X" at 13072.46,2057.64 h60
  text "V. SCORE" at 13259.46,2057.64 h60
  text "CERTIFICATION:" at 11332.46,1920.64 h60
  text "MATERIALS AND WORKMANSHIP FOR ALL PCBS" at 12057.46,1920.64 h60
  text "TO MEET OR EXCEED THE REQUIREMENTS OF:" at 12057.46,1822.64 h60
  text "X" at 11683.96,1686.13 h60
  text "ANSI IPC-A-600F CLASS ->" at 11822.96,1686.13 h60
  text "X" at 13462.02,1686.13 h60
  text "2" at 13580.96,1686.14 h60
  text "1" at 13265.96,1684.64 h60
  text "3" at 13934.96,1684.64 h60
  text "X" at 11686.02,1526.64 h60
  text "UL 94V-0" at 11822.96,1526.64 h60
  text "X" at 12498.02,1526.64 h60
  text "RoHS" at 12634.96,1526.64 h60
  text "OTHER" at 13279.36,1526.64 h60
  text "PER ORDER" at 13676.42,1526.64 h60
  text "ADDITIONAL REQUIREMENTS:" at 11332.46,1385.64 h60
  text "MICROSECTION:" at 11407.23,1270.64 h60
  text "YES" at 12312.96,1270.64 h60
  text "REQUIRED" at 13174.46,1114.49 h60
  text "BARE BOARD ELEC. TEST:" at 11407.23,1111.64 h60
  text "NONE" at 12712.96,1111.64 h60
  text "X" at 13047.46,1111.64 h60
  text "PER ORDER" at 13766.46,1111.64 h60
  text "MANUFACTURER'S UL:" at 11407.23,954.64 h60
  text "RAIL" at 12572.96,950.35 h60
  text "METAL" at 13064.77,950.35 h60
  text "X" at 13440,950 h60
  text "SILK" at 13576.46,950.35 h60
  text ".Layer_Name" at 577,-858.49 h60
M11 Gerber Information:
  lines w10: -292,-930.17 6308,-930.17 ; -292,-726.83 6310,-726.83 ; -292,-523.5 -292,-1133.5 3713,-1133.5 6310,-1133.5 6310,-523.5 -291.5,-523.5 -291.5,-1133.5 1284,-1133.5 ; 2173,-1133.5 2173,-523.5 ; 3440,-726.83 3440,-523.5 ; 4280,-726.83 4280,-523.5 ; 4902,-1140 4902,-937.17
  text "ALL ARTWORK VIEWED FROM TOP SIDE" at -228.5,-655.67 h60
  text "BOARD #:" at 2248,-655.67 h60
  text ".PRJ_Number" at 2793.5,-655.67 h60
  text "REV:" at 3638,-655.67 h60
  text ".PCB_Rev" at 3929.5,-655.67 h60
  text ".VersionControl_RevNumber" at 4982,-655.67 h60
  text "LAYER NAME =" at -228.5,-858.49 h60
  text "PLOT NAME =" at -228.5,-1064.34 h60
  text ".plot_File_Name" at 577,-1064.34 h60
  text "GENERATED    :" at 2250,-1064.34 h60
  text ".Print_Date" at 3119.5,-1064.34 h60
  text ".Print_Time" at 3848.5,-1064.34 h60
  text "TEXAS INSTRUMENTS" at 5113,-1064.34 h60
  text "SVN REV:" at 3826,-1130.67 h60
M12 Stackup:
  lines w5: 9570,7753.5 14225,7753.5 ; 9570,7848.7 14225,7848.7 ; 9510,6966 ccw(c9541,6966) 9541,6935 14254,6935 ccw(c14254,6966) 14285,6966 14285,7924 ccw(c14254,7924) 14254,7955 9541,7955 ccw(c9541,7924) 9510,7924 9510,6966
  text "Layer Stack Up Detail for: SAT0059.PcbDoc" at 9570,7871.55 h41
  text "Layer" at 9570,7813.2 h22
  text "Gerber" at 10479.66,7813.2 h22
  text "Copper" at 11089.49,7813.2 h22
  text "Dielectric" at 11735.24,7813.2 h22
  text "Dielectric" at 12396.38,7813.2 h22
  text "Dielectric" at 13151.1,7813.2 h22
  text "Dielectric" at 13812.24,7813.2 h22
  text "Name" at 9570,7769.2 h22
  text "Document" at 10479.66,7769.2 h22
  text "Thickness" at 11089.49,7769.2 h22
  text "Height" at 11735.24,7769.2 h22
  text "Material" at 12396.38,7769.2 h22
  text "Constant" at 13151.1,7769.2 h22
  text "Type" at 13812.24,7769.2 h22
  text "Top Solder Mask" at 9570,7706.38 h31
  text "(.GTS)" at 10479.66,7706.38 h31
  text "0.4mil" at 11735.24,7706.38 h31
  text "Solder Resist" at 12396.38,7706.38 h31
  text "3.50" at 13151.1,7706.38 h31
  text "Top Layer" at 9570,7617.12 h31
  text "(.GTL)" at 10479.66,7617.12 h31
  text "1.4mil" at 11089.49,7617.12 h31
  text "5.2mil" at 11735.24,7572.5 h31
  text "370HR" at 12396.38,7572.5 h31
  text "4.80" at 13151.1,7572.5 h31
  text "Core" at 13812.24,7572.5 h31
  text "GND" at 9570,7527.88 h31
  text "(.GP1)" at 10479.66,7527.88 h31
  text "1.4mil" at 11089.49,7527.88 h31
  text "5.2mil" at 11735.24,7483.25 h31
  text "370HR" at 12396.38,7483.25 h31
  text "4.80" at 13151.1,7483.25 h31
  text "PrePreg" at 13812.24,7483.25 h31
  text "Power" at 9570,7438.62 h31
  text "(.GP2)" at 10479.66,7438.62 h31
  text "1.4mil" at 11089.49,7438.62 h31
  text "30mil" at 11735.24,7394 h31
  text "370HR" at 12396.38,7394 h31
  text "4.80" at 13151.1,7394 h31
  text "Core" at 13812.24,7394 h31
  text "Inner Routing" at 9570,7349.38 h31
  text "(.G1)" at 10479.66,7349.38 h31
  text "1.4mil" at 11089.49,7349.38 h31
  text "5.2mil" at 11735.24,7304.75 h31
  text "370HR" at 12396.38,7304.75 h31
  text "4.80" at 13151.1,7304.75 h31
  text "PrePreg" at 13812.24,7304.75 h31
  text "GND 2" at 9570,7260.12 h31
  text "(.GP3)" at 10479.66,7260.12 h31
  text "1.4mil" at 11089.49,7260.12 h31
  text "5.2mil" at 11735.24,7215.5 h31
  text "370HR" at 12396.38,7215.5 h31
  text "4.80" at 13151.1,7215.5 h31
  text "Core" at 13812.24,7215.5 h31
  text "Bottom Layer" at 9570,7170.88 h31
  text "(.GBL)" at 10479.66,7170.88 h31
  text "1.4mil" at 11089.49,7170.88 h31
  text "Bottom Solder Mask" at 9570,7081.62 h31
  text "(.GBS)" at 10479.66,7081.62 h31
  text "0.4mil" at 11735.24,7081.62 h31
  text "Solder Resist" at 12396.38,7081.62 h31
  text "3.50" at 13151.1,7081.62 h31
  text ".Layer_Name" at 577,-858.49 h60
M13 Component Bodies Top:
  text ".Layer_Name" at 577,-858.49 h60
M14 Component Bodies Bottom:
  text ".Layer_Name" at 577,-858.49 h60
M15 Courtyards Top:
  text ".Layer_Name" at 577,-858.49 h60
M16 Courtyards Bottom:
  text ".Layer_Name" at 577,-858.49 h60
Drill Drawing:
  text ".legend" at 5596.86,985.5 h60
  text "Drill Table" at 5621.86,800.5 h60
  text ".Layer_Name" at 577,-858.49 h60

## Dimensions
-25.99,0.94 to -25.99,3090.94 on M2 Board Dimensions
0,0 to 3950,0 on M2 Board Dimensions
